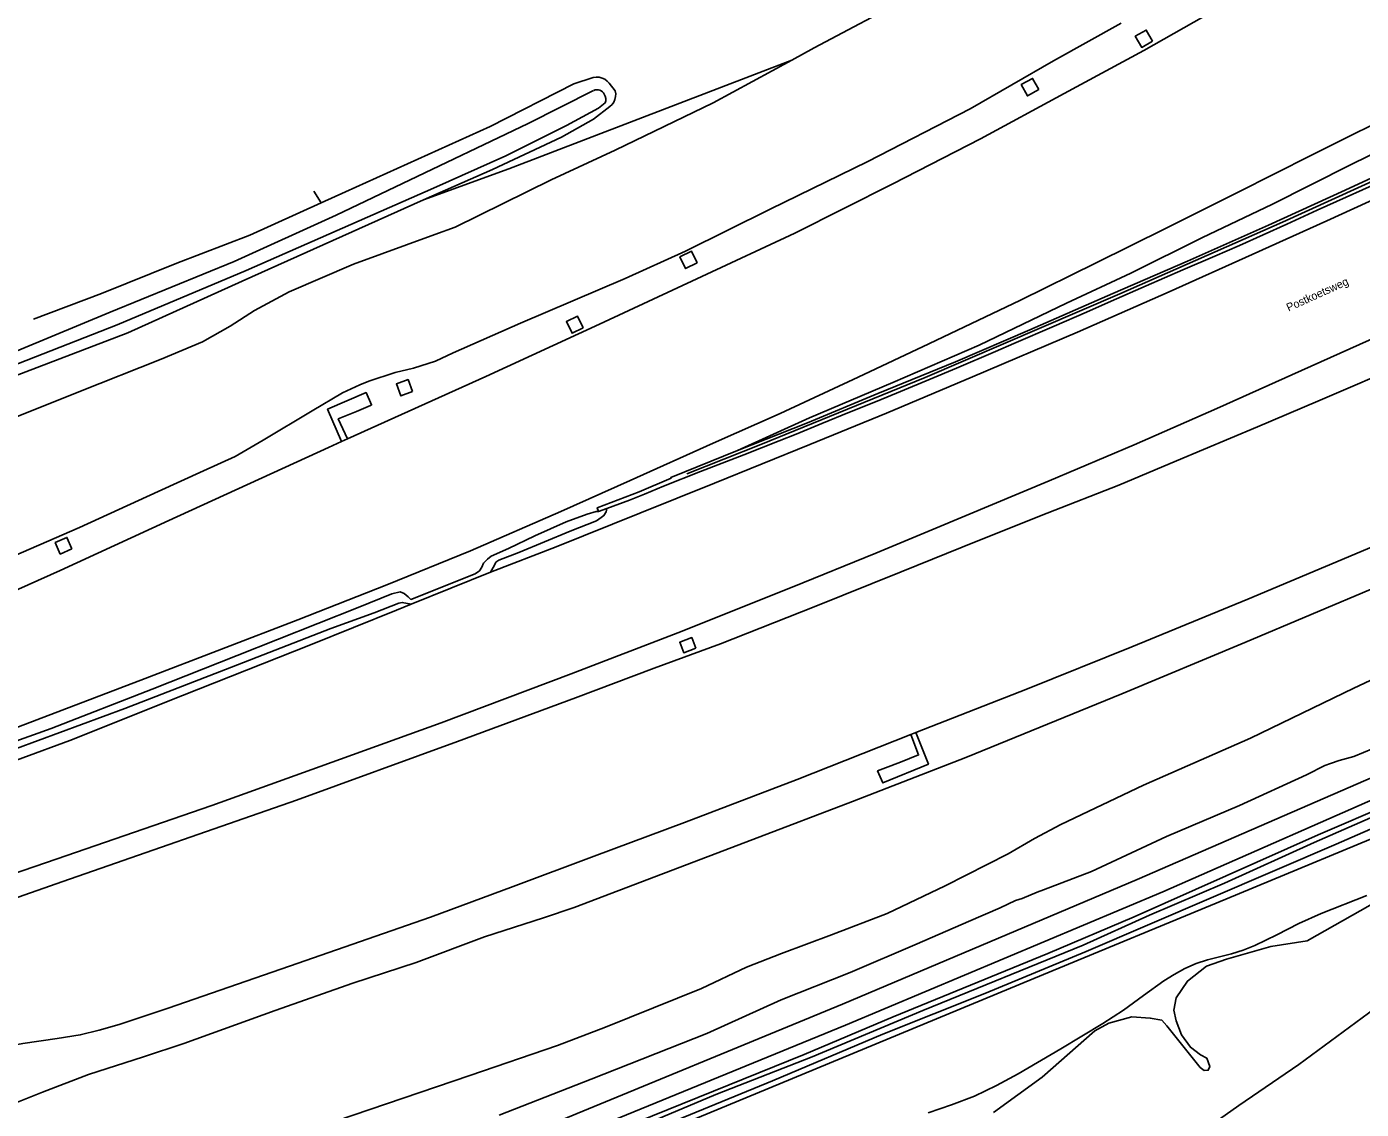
# Model space of a CAD drawing. Extents: x 156651 to 158072, y 387631 to 388990.
# Drawn here: x 156810.4 to 156977.2, y 388338.7 to 388473.9 of the extents above; entities that cross this region are included whole.
import ezdxf

# ---------------------------------------------------------------- set-up
doc = ezdxf.new("R2010")
doc.units = 0
for name, color, linetype in [('IMGEO_Berm_groen', 7, 'Continuous'), ('IMGEO_Geluidsscherm', 7, 'Continuous'), ('IMGEO_Grasland_overig', 7, 'Continuous'), ('IMGEO_Groenvoorziening', 7, 'Continuous'), ('IMGEO_Loofbos', 7, 'Continuous'), ('IMGEO_Meer_plas_ven_vijver', 7, 'Continuous'), ('IMGEO_Muur', 7, 'Continuous'), ('IMGEO_Openbare_ruimte_label', 7, 'Continuous'), ('IMGEO_Rijbaan_autosnelweg', 7, 'Continuous'), ('IMGEO_Waterloop', 7, 'Continuous')]:
    doc.layers.add(name, color=color, linetype=linetype)

msp = doc.modelspace()

# ---------------------------------------------------------------- linework, layer by layer
at = {"layer": 'IMGEO_Berm_groen'}
for points in [[(156806.8, 388406.92), (156816.98, 388411.36), (156826.82, 388415.86), (156832.47, 388418.41), (156836.46, 388420.23), (156839.93, 388422.25), (156846.08, 388425.9), (156849.84, 388428.17), (156852.01, 388429.17), (156853.13, 388429.61), (156856.45, 388430.71), (156858.74, 388431.24), (156861.49, 388432.11), (156863.69, 388433.18), (156872.11, 388436.88), (156885.19, 388442.45), (156892.7, 388445.88), (156903.29, 388451.09), (156915.5, 388457.07), (156928.31, 388463.65), (156938.72, 388469.65), (156947.17, 388474.36)], [(157007.15, 388472.46), (156997.78, 388467.5), (156990.09, 388463.75), (156982.54, 388459.93), (156975.84, 388456.64), (156966.01, 388451.68), (156957.34, 388447.55), (156948.37, 388443.12), (156940.34, 388439.35), (156929.41, 388434.11), (156918.63, 388429.47), (156908.2, 388425.05), (156899.21, 388420.97)], [(156951.09, 388472.1), (156949.73, 388471.31), (156948.93, 388472.7), (156950.3, 388473.48), (156951.09, 388472.1)], [(156936.87, 388466.04), (156935.45, 388465.26), (156934.68, 388466.66), (156936.1, 388467.44), (156936.87, 388466.04)], [(156894.19, 388444.39), (156892.73, 388443.69), (156892.03, 388445.15), (156893.49, 388445.85), (156894.19, 388444.39)], [(156879.95, 388436.28), (156878.54, 388435.6), (156877.83, 388437.06), (156879.24, 388437.74), (156879.95, 388436.28)], [(156858.62, 388428.33), (156857.15, 388427.78), (156856.59, 388429.27), (156858.06, 388429.82), (156858.62, 388428.33)], [(157033.61, 388428.04), (157015.46, 388419.85), (156996.46, 388411.35), (156994.09, 388410.39), (156979.21, 388403.98), (156962.6, 388397), (156947.24, 388390.55), (156927.76, 388382.6), (156913.61, 388377.12), (156901.15, 388372.37), (156878.79, 388363.87), (156874.96, 388362.57), (156867.6, 388360.22), (156859.06, 388356.99), (156851.16, 388354.43), (156841.43, 388351), (156830.03, 388346.88), (156824.99, 388345.22), (156818.1, 388343.02), (156812.37, 388340.8), (156808.83, 388339.39)], [(156849.75, 388422.1), (156847.98, 388426.11), (156852.81, 388428.2), (156853.48, 388426.66), (156853.34, 388426.6), (156851.59, 388425.83), (156849.33, 388424.9), (156850.49, 388422.43)], [(156881.85, 388413.33), (156881.57, 388413.36), (156880.45, 388413.01), (156877.8, 388412.06), (156873.87, 388410.32), (156870.6, 388408.71), (156868.44, 388407.77), (156867.96, 388407.4), (156867.49, 388406.87), (156867.27, 388406.38), (156866.97, 388405.95), (156866.43, 388405.57), (156858.39, 388402.37), (156858.08, 388402.69), (156857.57, 388403.1), (156857.06, 388403.29), (156856.02, 388403.06), (156851.83, 388401.37), (156836.7, 388395.36), (156826.07, 388391.14), (156813.45, 388386.25), (156800.61, 388381.67)], [(156882.88, 388413.71), (156882.82, 388413.31), (156882.52, 388412.83), (156882.18, 388412.59), (156881.59, 388412.19), (156878.31, 388410.9), (156871.89, 388408.22), (156869.39, 388407.27), (156869.02, 388407), (156868.84, 388406.65), (156868.34, 388405.78)], [(156816.04, 388408.66), (156814.58, 388408.03), (156813.96, 388409.47), (156815.42, 388410.1), (156816.04, 388408.66)], [(156794.54, 388378.62), (156797.64, 388379.76), (156809.13, 388383.76), (156822.66, 388388.72), (156835.23, 388393.6), (156848.38, 388398.74), (156853.81, 388400.67), (156856.88, 388401.89), (156857.32, 388401.99), (156858.45, 388401.76)], [(156894.02, 388396.28), (156893.51, 388397.59), (156892.01, 388397.01), (156892.51, 388395.7), (156894.02, 388396.28)], [(156920.86, 388385.47), (156921.84, 388382.93), (156919.57, 388382.04), (156917.72, 388381.32), (156916.72, 388380.94), (156917.39, 388379.44), (156923.08, 388381.79), (156921.5, 388385.72)]]:
    msp.add_lwpolyline(points, dxfattribs=at)
at = {"layer": 'IMGEO_Geluidsscherm'}
msp.add_lwpolyline([(157014.29, 388471.54), (156992.28, 388460.85), (156967.33, 388449.48), (156947.01, 388440.53), (156922.68, 388430.09), (156902.14, 388421.71), (156892.89, 388418.06)], dxfattribs=at)
at = {"layer": 'IMGEO_Grasland_overig'}
for points in [[(156905.99, 388469.73), (156896.16, 388464.39), (156883.95, 388458.48), (156875.92, 388454.77), (156863.94, 388448.86), (156861.41, 388447.94), (156851.24, 388444.25), (156843.21, 388440.8), (156838.85, 388438.47), (156835.8, 388436.51), (156832.36, 388434.52), (156827.18, 388432.39), (156816.89, 388428.3), (156806.15, 388424)], [(156811.25, 388437.37), (156819.73, 388440.57), (156829.16, 388444.36), (156838.28, 388447.85), (156847.18, 388451.89)], [(157038.44, 388420.38), (157025.01, 388413.81), (157013.87, 388408.68), (157002.19, 388403.46), (156993.89, 388399.62), (156984.41, 388395.12), (156976.25, 388391.29), (156963.34, 388385.05), (156949.96, 388379.15), (156939.63, 388374.23), (156936.32, 388372.48), (156933.06, 388370.6), (156925.18, 388366.57), (156917.92, 388363.15), (156910.98, 388360.46), (156904.72, 388358.14), (156900.35, 388356.43), (156894.7, 388353.75), (156882.73, 388348.95), (156876.74, 388346.66), (156865.75, 388342.89), (156849.11, 388337.25), (156838.9, 388333.53), (156830.4, 388330.8)], [(156869.45, 388337.92), (156880.91, 388342.44), (156895.38, 388348.16), (156904.68, 388352.35), (156913.29, 388355.78), (156921.67, 388359.36), (156928.08, 388362.13), (156932.05, 388363.82), (156933.98, 388364.77), (156934.81, 388365.01), (156936.68, 388365.81), (156937.47, 388366.07), (156943.45, 388368.36), (156952.83, 388372.75), (156961.96, 388376.6), (156970.33, 388380.47), (156972.6, 388381.61), (156973.32, 388381.87), (156974.39, 388382.23), (156976.23, 388382.75), (156981.06, 388384.74)]]:
    msp.add_lwpolyline(points, dxfattribs=at)
at = {"layer": 'IMGEO_Groenvoorziening'}
for points in [[(156769.11, 388416.9), (156770.47, 388417.27), (156795.55, 388425.15), (156823.01, 388435.66), (156837.32, 388442.11), (156859.98, 388452.29)], [(156865.15, 388270.87), (156882.49, 388283.2), (156947.52, 388329.05), (156961.89, 388339.16), (156969.37, 388344.28), (156978.86, 388351.25), (156984.42, 388354.41), (157034.33, 388380.44), (157049.06, 388388.29), (157064.03, 388395.89), (157078.36, 388403.52), (157095.1, 388412.16), (157109.23, 388419.11), (157109.33, 388419.03), (157109.47, 388419.11), (157130.07, 388429.76), (157152.82, 388441.83)], [(157099.84, 388435.72), (157085.05, 388428.2), (157058.57, 388415.01), (157050.12, 388410.81), (157036.58, 388404.15), (157015.78, 388393.58), (157010.27, 388390.87), (157004.7, 388388.13), (157002.73, 388387.16), (156993.89, 388382.92), (156980.9, 388376.88), (156971.77, 388372.96), (156948.79, 388362.73), (156938.01, 388358.15), (156918.68, 388350.24), (156907.55, 388345.5), (156882.93, 388335.55)], [(156878.22, 388331.81), (156903.6, 388342.23), (156917.4, 388348.06), (156930.12, 388353.14), (156942.81, 388358.37), (156974.02, 388371.79), (156980.99, 388374.83), (156988.64, 388378.32), (156999.96, 388383.71), (157002.79, 388384.94), (157005.01, 388386.02), (157008.67, 388388.04), (157017.86, 388392.5), (157029.51, 388398.47), (157040.41, 388403.8), (157060.97, 388414.07), (157068.59, 388417.98), (157075.32, 388421.02), (157092.73, 388430.42), (157101.58, 388434.8)], [(156883.26, 388334.96), (156896.51, 388340.51), (156908.55, 388345.24), (156922.37, 388351.02), (156942.41, 388359.16), (156950.71, 388362.93), (156960.07, 388366.92), (156971.3, 388372), (156993.45, 388381.69)], [(156978.28, 388364.17), (156970.43, 388359.73), (156965.86, 388359), (156960.34, 388357.41), (156957.81, 388356.55), (156955.45, 388354.69), (156954.02, 388352.58), (156953.75, 388351.05), (156954.03, 388349.73), (156954.71, 388347.96), (156955.83, 388346.43), (156957.08, 388345.48), (156957.89, 388345.04), (156958.24, 388344), (156958.05, 388343.56), (156957.55, 388343.52), (156957.02, 388343.9), (156952.89, 388349.11), (156952.24, 388349.81), (156950.8, 388350.06), (156948.49, 388350.21), (156945.64, 388349.42), (156943.87, 388348.48), (156937.31, 388342.69), (156931.22, 388338.28)]]:
    msp.add_lwpolyline(points, dxfattribs=at)
at = {"layer": 'IMGEO_Loofbos'}
for points in [[(156905.99, 388469.73), (156908.78, 388471.24), (156920.93, 388477.71), (156931.97, 388484.3), (156932.53, 388484.57)], [(156859.98, 388452.29), (156870.65, 388456.15), (156901.35, 388467.94), (156905.99, 388469.73)], [(156847.18, 388451.89), (156850.24, 388453.27), (156868.29, 388461.43), (156878.75, 388466.77), (156881.2, 388467.55), (156881.57, 388467.6), (156881.94, 388467.58), (156882.3, 388467.48), (156882.64, 388467.33), (156882.94, 388467.11), (156883.2, 388466.84), (156883.95, 388465.88), (156884, 388465.53), (156883.99, 388465.17), (156883.9, 388464.82), (156883.75, 388464.49), (156883.54, 388464.19), (156883.28, 388463.95), (156881.21, 388462.35), (156877.22, 388460.12), (156868.61, 388456.05), (156859.98, 388452.29)], [(156846.28, 388453.35), (156847.18, 388451.89)]]:
    msp.add_lwpolyline(points, dxfattribs=at)
at = {"layer": 'IMGEO_Meer_plas_ven_vijver'}
for points in [[(157112.6, 388439.56), (157079.41, 388422), (157037.94, 388401.59), (157010.38, 388387.89), (156983.94, 388374.74), (156960.26, 388364.94), (156937.46, 388355.51), (156903.18, 388341.32), (156879.22, 388331.41)], [(156923.06, 388338.22), (156925.96, 388339.22), (156928.83, 388340.33), (156931.6, 388341.65), (156934.3, 388343.12), (156939.61, 388346.23), (156944.88, 388349.38), (156947.46, 388351.07), (156949.97, 388352.9), (156952.5, 388354.7), (156953.8, 388355.52), (156955.13, 388356.25), (156956.52, 388356.87), (156957.97, 388357.34), (156960.96, 388358.11), (156962.42, 388358.57), (156963.85, 388359.12), (156966.62, 388360.45), (156969.36, 388361.87), (156972.15, 388363.15), (156977.87, 388365.39)]]:
    msp.add_lwpolyline(points, dxfattribs=at)
at = {"layer": 'IMGEO_Muur'}
for points in [[(156899.21, 388420.97), (156907.95, 388424.4), (156916.76, 388428.07), (156926.46, 388432.03), (156935.76, 388436.03), (156946.13, 388440.58), (156955.46, 388444.63), (156965.58, 388449.09), (156975.18, 388453.48), (156984.62, 388457.85), (156993.86, 388462.13), (157002.68, 388466.38), (157008.82, 388469.4)], [(156979.38, 388454.46), (156975.28, 388452.6), (156971.67, 388450.97), (156967.85, 388449.24), (156961.97, 388446.58), (156958.86, 388445.23), (156954.89, 388443.51), (156950.31, 388441.53), (156945.91, 388439.6), (156942.85, 388438.26), (156938.8, 388436.5), (156933.76, 388434.32), (156931.48, 388433.31), (156926.6, 388431.26), (156923.31, 388429.87), (156919.59, 388428.33), (156916.67, 388427.13), (156913.22, 388425.75), (156909.74, 388424.32), (156906.57, 388423.02), (156904.43, 388422.19), (156900.02, 388420.44), (156894.61, 388418.32), (156889.97, 388416.5), (156887.59, 388415.49), (156885.73, 388414.76), (156882.88, 388413.71)], [(156881.85, 388413.33), (156881.69, 388413.82), (156886.93, 388415.81), (156890.91, 388417.49), (156890.87, 388417.58), (156899.21, 388420.97)], [(157109.47, 388419.11), (157109.33, 388419.03), (157109.23, 388419.11), (157095.1, 388412.16), (157078.36, 388403.52), (157064.03, 388395.89), (157049.06, 388388.29), (157034.33, 388380.44), (156984.42, 388354.41), (156978.86, 388351.25), (156969.37, 388344.28), (156961.89, 388339.16), (156947.52, 388329.05), (156882.49, 388283.2), (156865.15, 388270.87)], [(156882.88, 388413.71), (156881.85, 388413.33)]]:
    msp.add_lwpolyline(points, dxfattribs=at)
at = {"layer": 'IMGEO_Rijbaan_autosnelweg'}
for points in [[(156850.49, 388422.43), (156867.76, 388430.19), (156881.96, 388436.76), (156894.76, 388442.7), (156906.39, 388448.11), (156918.61, 388454.27), (156929.57, 388459.9), (156940.05, 388465.55), (156949.99, 388470.91), (156960, 388476.61), (156969.53, 388482.08)], [(157007.54, 388476.45), (156996.13, 388470.49), (156983.49, 388464.1), (156970.96, 388457.85), (156961.71, 388453.19), (156952.7, 388448.71), (156944.05, 388444.41), (156934.6, 388439.76), (156923.12, 388434.3), (156914.3, 388430.13), (156904.54, 388425.59), (156896.18, 388421.86), (156885.8, 388417.21), (156877.15, 388413.34), (156865.83, 388408.45), (156855.39, 388404.17), (156844.26, 388399.83), (156825.18, 388392.5), (156808.5, 388386.13), (156789.68, 388379.33), (156777.96, 388375.51)], [(156868.34, 388405.78), (156876.54, 388408.92), (156887.02, 388413.15), (156896.35, 388416.89), (156908.24, 388421.72), (156917.83, 388425.64), (156928.57, 388430.18), (156941.71, 388435.76), (156953.18, 388440.8), (156963.54, 388445.45), (156972.87, 388449.66), (156984.9, 388455.13), (156997.04, 388460.87), (157007.12, 388465.76), (157018.15, 388471.1)], [(157014.5, 388451.76), (157003.5, 388446.5), (156992.38, 388441.29), (156979.35, 388435.29), (156969.69, 388430.95), (156959.11, 388426.22), (156948.77, 388421.67), (156938.16, 388417.16), (156924, 388411.27), (156916.49, 388408.14), (156906.04, 388403.91), (156891.77, 388398.2), (156878.43, 388393.06), (156862.19, 388386.95), (156847.05, 388381.48), (156833.53, 388376.62), (156814.07, 388369.9), (156798.99, 388364.76), (156787.53, 388360.64)], [(157028.04, 388451.87), (157013.91, 388445.5), (157004.39, 388441.28), (156992.56, 388436.09), (156983.19, 388432.04), (156971.74, 388427.13), (156964.19, 388423.91), (156954.06, 388419.68), (156946.89, 388416.65), (156937.92, 388413.15), (156929.26, 388409.66), (156919.68, 388405.8), (156908.82, 388401.43), (156897.09, 388396.8), (156888.81, 388393.79), (156878.97, 388390.08), (156864.24, 388384.6), (156844.11, 388377.29), (156814.9, 388367.13), (156799.67, 388361.79), (156791.61, 388358.82)], [(156921.5, 388385.72), (156935.44, 388391.19), (156948.48, 388396.42), (156962.98, 388402.39), (156977.97, 388408.69), (156990.72, 388414.12), (157001.63, 388418.86), (157011.73, 388423.29), (157025.45, 388429.48)], [(156771.25, 388388.98), (156775.85, 388390.44), (156786.27, 388394.19), (156798.65, 388399.06), (156805.32, 388401.87), (156814.58, 388405.96), (156828.17, 388412.24), (156848.1, 388421.35), (156849.75, 388422.1)], [(156849.75, 388422.1), (156850.49, 388422.43)], [(156858.45, 388401.76), (156868.34, 388405.78)], [(156779.49, 388373.23), (156782.47, 388374.18), (156785.49, 388374.81), (156790.59, 388375.66), (156791.55, 388375.79), (156803.97, 388380.42), (156815.76, 388384.72), (156829.87, 388390.36), (156845.86, 388396.71), (156856.6, 388401.01), (156858.45, 388401.76)], [(156802.01, 388344.99), (156804.07, 388345.74), (156806.57, 388346.25), (156809.92, 388346.9), (156814.18, 388347.53), (156817.08, 388347.97), (156819.45, 388348.55), (156821.94, 388349.28), (156828.07, 388351.3), (156843.23, 388356.57), (156860.84, 388362.69), (156871.2, 388366.51), (156881.31, 388370.31), (156892.61, 388374.48), (156906.67, 388379.86), (156920.86, 388385.47)], [(156921.5, 388385.72), (156920.86, 388385.47)]]:
    msp.add_lwpolyline(points, dxfattribs=at)
at = {"layer": 'IMGEO_Waterloop'}
for points in [[(157255.73, 388475.57), (157234.03, 388469.8), (157227.42, 388468.47), (157206.21, 388464.02), (157191.75, 388460.81), (157177.09, 388457.97), (157166.17, 388455.97), (157148.59, 388454.12), (157135.71, 388453.17), (157132.29, 388452.56), (157126.35, 388450.57), (157122.08, 388448.64), (157095.06, 388434.67), (157062.94, 388418.86), (157022.7, 388398.41), (156983.81, 388379.68), (156952.39, 388365.84), (156912.72, 388349.17), (156867.85, 388330.81), (156853.8, 388325.37), (156843.63, 388321.46), (156840.61, 388320.22), (156839.96, 388319.7)], [(156769.26, 388420.3), (156791.28, 388427.19), (156805.96, 388432.08), (156820.84, 388438.25), (156836.3, 388444.59), (156849.06, 388450.37), (156857.35, 388454.3), (156873.06, 388461.79), (156881.24, 388465.94)], [(156882.7, 388464.37), (156881.83, 388463.72), (156877.83, 388461.54), (156870.26, 388457.75), (156861.24, 388453.75), (156837.83, 388443.43), (156821.71, 388436.68), (156806.24, 388430.61), (156792.15, 388425.63), (156770.54, 388418.6)], [(156860.99, 388280.79), (156849.65, 388298.94), (156841.49, 388312.58), (156839.71, 388315.71), (156837.04, 388320.29), (156836.88, 388321.3), (156837.18, 388321.85), (156837.84, 388322.55), (156839.05, 388323.06), (156841.72, 388323.59), (156843.92, 388323.76), (156875.13, 388336.49), (156912.34, 388351.81), (156949.18, 388367.37), (156982.81, 388381.99), (157017.47, 388398.46), (157045.56, 388412.8), (157068.76, 388424.09), (157098.17, 388438.71), (157125.48, 388452.43)]]:
    msp.add_lwpolyline(points, dxfattribs=at)
for centre, radius, start, end in [((156881.67, 388465.06), 0.972, 24.3914, 115.8745), ((156881.69, 388464.79), 1.09, 337.3849, 37.8595)]:
    msp.add_arc(centre, radius, start, end, dxfattribs=at)

# ---------------------------------------------------------------- texts
at = {"layer": 'IMGEO_Openbare_ruimte_label'}
msp.add_text('Postkoetsweg', height=1, rotation=24.2591, dxfattribs=at).set_placement((156968.09, 388438.31))

doc.saveas('drawing.dxf')
